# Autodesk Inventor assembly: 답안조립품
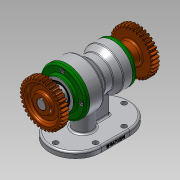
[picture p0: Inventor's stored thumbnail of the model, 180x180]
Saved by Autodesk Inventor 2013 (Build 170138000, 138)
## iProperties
Created: 2020-01
Part Number: 답안조립품
Document SubType Name: Assembly
Designer: Administrator
Author: Administrator
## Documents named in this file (13)
- C:\Users\Administrator\Desktop\700104V1019\답안조립품.iam
- C:\Users\Administrator\Desktop\700104V1019\본체.ipt
- C:\Users\Administrator\Desktop\700104V1019\뒤커버.ipt
- C:\Users\Administrator\Desktop\700104V1019\멈춤나사 M3.ipt
- C:\Users\Administrator\Desktop\700104V1019\베어링 6203.ipt
- C:\Users\Administrator\Desktop\700104V1019\베어링 6205.ipt
- C:\Users\Administrator\Desktop\700104V1019\볼트 M4.ipt
- C:\Users\Administrator\Desktop\700104V1019\스퍼기어.ipt
- C:\Users\Administrator\Desktop\700104V1019\앞커버.ipt
- C:\Users\Administrator\Desktop\700104V1019\오일 실 17 30 8.ipt
- C:\Users\Administrator\Desktop\700104V1019\오일 실 25 38 8.ipt
- C:\Users\Administrator\Desktop\700104V1019\축.ipt
- C:\Users\Administrator\Desktop\700104V1019\키 5 x 5 x 18.ipt
